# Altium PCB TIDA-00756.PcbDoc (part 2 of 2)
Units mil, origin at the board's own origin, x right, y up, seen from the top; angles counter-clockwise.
Board outline 4100 x 1700 mil, 4 copper layers (Top Layer, Signal Layer 1, Signal Layer 2, Bottom Layer), stack 43.668 mil thick; 130 components, 51 nets, 280 pads, 420 vias.
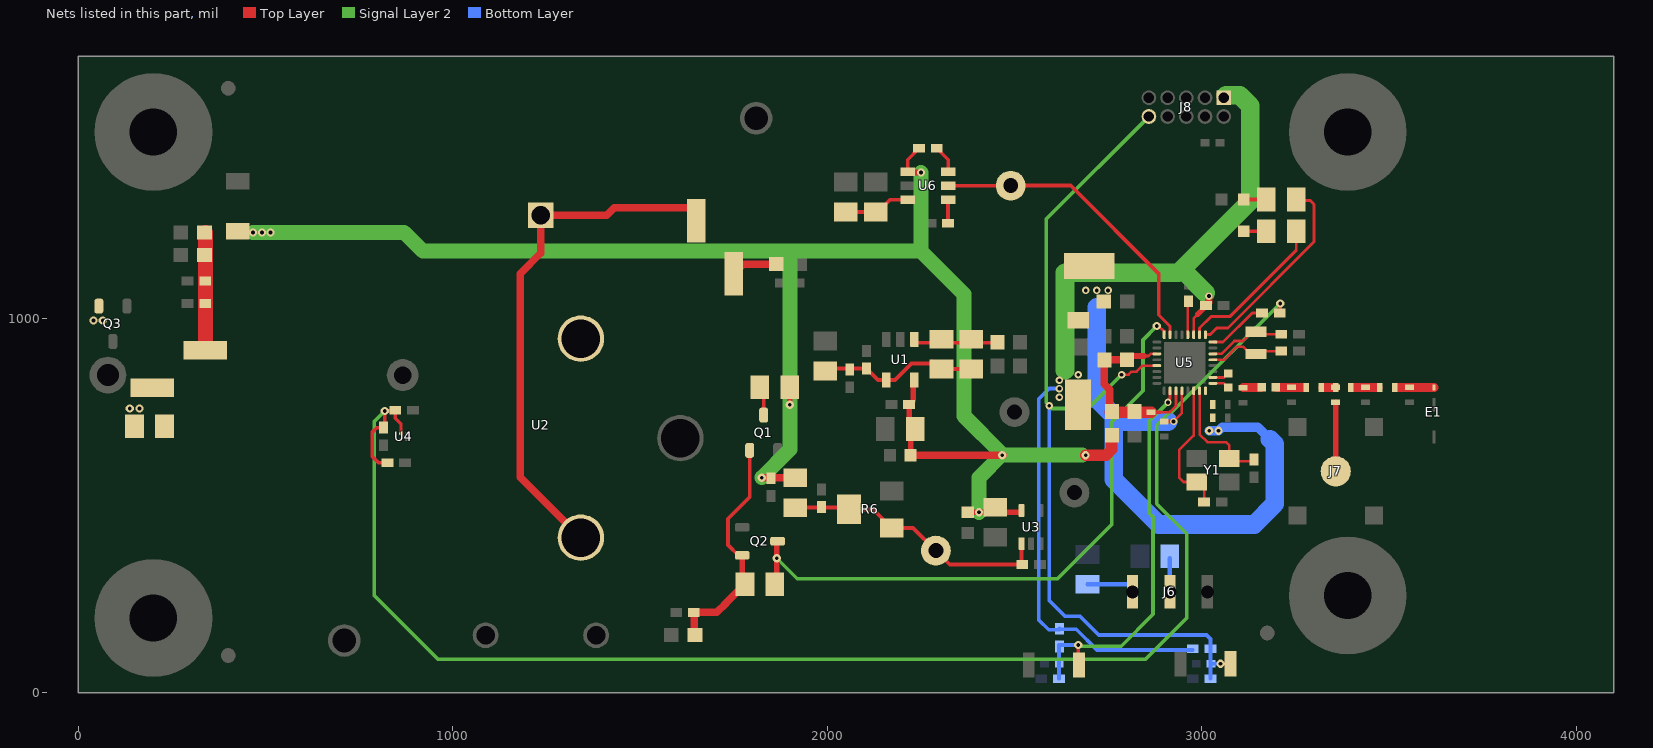
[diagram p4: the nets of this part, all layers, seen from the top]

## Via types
v1: diameter 26, hole 10, Top Layer to Bottom Layer, tented both sides, 253 vias
v2: diameter 20, hole 10, Top Layer to Bottom Layer, tented both sides, 105 vias
v3: diameter 22, hole 10, Top Layer to Bottom Layer, tented both sides, 57 vias
v4: diameter 19.68, hole 7.87, Top Layer to Bottom Layer, 5 vias

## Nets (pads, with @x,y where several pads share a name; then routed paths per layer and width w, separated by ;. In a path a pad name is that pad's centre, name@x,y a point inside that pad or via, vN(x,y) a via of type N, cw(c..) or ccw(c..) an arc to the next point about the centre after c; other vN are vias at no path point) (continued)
NetC6_1: C6.1 Q1.1 Q2.2 R3.2 R5.1 | length 633
  Top Layer w10: Q2.2@1772.76,367.6 1771.54,366.38 1763.62,366.38 1735,395 1735,465 1792.6,522.6 Q1.1@1792.6,647.76
  Top Layer w15: R5.1@1772.76,297.24 Q2.2@1772.76,367.6
  Top Layer w20: C6.1@1643.62,215 C6.1@1645,215 ; R3.2@1645,153.62 C6.1@1645,215 ; 1725,235 R5.1@1780,290 ; 1730,240 1705,215 C6.1@1645,215
NetC21_1: C21.1 R13.1 R14.1 | length 34
  Top Layer w24: C21.1@3324,816.3 R14.1@3358,816.3
NetC21_2: C21.2 C24.1 L2.2 | length 74.4
  Top Layer w24: L2.2@3199.65,816.3 C24.1@3240,816.3 C21.2@3274,816.3
NetC23_1: C23.1 L1.2 L2.1 U5.1 | length 90.3
  Top Layer w7: U5.1@3029.8,826.88 3059.12,826.88 L1.2@3069.7,816.3
  Top Layer w24: C23.1@3112,816.3 L2.1@3158,816.3
NetC25_2: C25.2 R14.2 R15.1 | length 68
  Top Layer w24: R14.2@3403,816.3 C25.2@3437,816.3 R15.1@3471,816.3
NetC26_2: C26.2 E1.1 R15.2 | length 99.3
  Top Layer w24: R15.2@3521,816.3 C26.2@3555,816.3 E1.1@3620.31,816.3
NetC27_1: C27.1 U5.12 | length 89.6
  Top Layer w7: U5.12@2962.87,956.8 C27.1@2962.87,1046.38
NetD1_1: D1.1 R22.2 | length 60.4
  Top Layer w10: D1.1@3112.09,1317.87 R22.2@3172.44,1317.87
NetD2_1: D2.1 R23.2 | length 60.4
  Top Layer w10: D2.1@3112.09,1232.87 R23.2@3172.44,1232.87
NetJ1_2: J1.2 R1.1 | length 124.2
  Top Layer w20: J1.2@1750,1119.13 1775.87,1145 R1.1@1863.5,1145
NetJ2_1: J2.1 R7.2
NetJ7_1: J7.1 R13.2 | length 184.7
  Top Layer w15: J7.1@3358,591.63 R13.2@3358,776.3
NetL1_1: L1.1 U5.2 | length 45.5
  Top Layer w7: U5.2@3029.8,842.63 3059.63,842.63 L1.1@3070.7,853.7
NetQ1_3: Q1.3 R2.2 | length 77.8
  Top Layer w10: Q1.3@1830,742.24 R2.2@1830,820
NetQ3_2: Q3.2 R7.1
  other v3: 137,760 163,760 40,995 65,995
NetR11_1: R11.1 U5.8 | length 163.8
  Top Layer w7.8: U5.8@3029.8,937.12 3057.12,937.12 3135,1015 R11.1@3161.38,1015
NetR16_1: R16.1 U6.6 | length 75.2
  Top Layer w10: R16.1@2292.56,1454.69 2323.07,1424.17 U6.6@2323.07,1392.09
NetR17_2: R17.2 R18.1 U6.3 | length 179.4
  Top Layer w10: R17.2@2048.94,1284.68 R18.1@2128.94,1284.69 2134.69,1284.69 2167.28,1317.28 U6.3@2214.8,1317.28
NetR19_2: R19.2 U6.4 | length 62.8
  Top Layer w10: R19.2@2322.56,1254.69 2322.56,1316.77 U6.4@2323.07,1317.28
NRESET: C36.2 J8.10 R21.1 S2.2 U5.21 U10.1 | length 2378.6
  Top Layer w7: v2(2786,850) 2805,850 2813,858 2826,858 2842.13,874.13 U5.21@2880.2,874.13
  Top Layer w10: v3(3050,78) S2.2@3076.93,78
  Signal Layer 2 w10: v2(2786,850) 2696,760 2600,760 v2(2593,767) 2585,775 2585,1265.75 J8.10@2858.94,1539.69
  Bottom Layer w10: v2(2593,767) 2593,247 2635,205 2675,205 2725,155 3013,155 3023.62,144.38 R21.1@3023.62,118 C36.2@3023.62,38 ; U10.1@3024.68,78 v3(3050,78)
RE: J5.1
RLED: R22.1 U5.9 | length 543.9
  Top Layer w7.8: U5.9@3010.12,956.8 3021.8,956.8 3040,975 3070,975 3300,1205 3300,1305 3290,1315 3260,1315 R22.1@3255,1310
SENSOR_TEST: Q2.3 R5.2 U5.16 | length 1707.8
  Top Layer w7.8: v3@2885,980 2899.88,965.12 U5.16@2899.88,956.8
  Top Layer w8: v3(2880,980) v3@2885,980
  Top Layer w10: Q2.3@1865,402.76 Q2.3@1867.24,405
  Top Layer w15: R5.2@1865,290 v3(1865,360) Q2.3@1865,402.76
  Signal Layer 2 w10: v3(1865,360) 1920,305 2615,305 2760,450 2760,724 2843,807 2843,943 v3(2880,980)
THRESH: C5.2 C8.1 R4.1 R6.1 R6.2 TP3.1 U3.1 | length 717
  Top Layer w10: R4.1@1920,495 R6.2@2050,495 ; R6.2@2057.91,490 2122.87,490 R6.1@2172.09,440.79 ; R6.1@2175,437.87 2175,440 2172.87,440 R6.1@2172.09,440.79 ; U3.1@2518.91,398.71 2518.91,344.97 C5.2@2520.88,343 ; C5.2@2520,342.12 C5.2@2520.88,343 ; R6.1@2172.09,440.79 2229.21,440.79 TP3.1@2290,380 2327,343 C5.2@2520.88,343
TIA_IN: C1.2 C3.1 CF1.2 RF1.1 RL1.2 U1.4 | length 456.5
  Top Layer w10: RL1.2@1995,873.62 2002.24,866.38 C3.1@2105,866.38 2135.67,835.71 2180.71,835.71 2225,880 2290,880 RF1.1@2300,870 ; RF1.1@2280,885 2300,865 RF1.1@2305,865 CF1.2@2385,865
TIA_OUT: CF1.1 RF1.2 RO1.1 U1.1 | length 205.6
  Top Layer w10: U1.1@2235,935 RO1.1@2436.61,935 ; RO1.1@2452.2,939.29 RO1.1@2455,936.5
UART_RX: J6.1 R10.1 | length 150
  Bottom Layer w12: R10.1@2695,290 2815,290 J6.1@2815,260
UART_TX: J6.2 R12.1 | length 100
  Bottom Layer w12: J6.2@2915,260 R12.1@2915,360
USR_BTN: C35.2 R20.1 S1.2 U5.26 U9.1 | length 1052.6
  Top Layer w7.8: v2@2906,776 2915.63,785.63 U5.26@2915.63,807.2
  Top Layer w10: S1.2@2670,75 v3@2670,129.93
  Signal Layer 2 w10: v3@2675,125 2785,125 2870,210 2870,470 2860,480 2860,726 v2(2910,776)
  Bottom Layer w10: C35.2@2618.62,38 2618.62,128 v3(2670,128)
V_BATT: C7.1 C9.2 C10.2 C11.1 C12.2 C13.2 C14.1 C15.1 C16.1 C17.1 C18.1 J2.2 L3.1 R2.1 R4.2 R16.2 U1.5 U3.5 U6.1 | length 4929.7
  Top Layer w10: U6.1@2214.8,1392.09 2214.8,1424.17 R16.2@2245.31,1454.69 ; U3.5@2514.18,482.56 U3.5@2518.91,487.29
  Top Layer w15: v3(1900,770) R2.1@1900,816.12 ; U6.1@2216.89,1390 v3(2250,1390) ; C9.2@2222.56,635 2222.56,692.56 C10.2@2235,705 2218.62,721.38 C11.1@2218.62,770 2230,781.38 U1.5@2230,826.3 ; C12.2@2385,482.56 v3(2405,482.56) U3.5@2514.18,482.56
  Top Layer w20: v3(1825,575) R4.2@1905,575 ; C9.2@2222.56,635 v3(2467.56,635) v3@2470,635
  Top Layer w30: v3(2690,635) 2745,635 2760,650 L3.1@2760,688.5
  Top Layer w40: J2.2@339,928 C15.1@339,1230
  Signal Layer 2 w40: v3(466,1230) 870,1230 920,1180 2250,1180 v3(2250,1390) ; v3(1825,575) 1900,650 1900,1180 ; 2245,1185 2365,1065 2365,740 2467.5,637.5 2405,575 v3(2405,482.56) ; v3@2465,635 v3@2681,635
  other v3: 490,1230 513,1230
VCC_I2C: C19.1 R8.2 R9.2 R11.2 U4.A1 | length 4114.6
  Top Layer w8: U4.A1@860.83,694 860.83,719.17
  Top Layer w10: R9.2@815,708.62 818,711.62 v3(818,753) 837,753 C19.1@839,755 ; R9.2@818.7,708.54 796.54,708.54 785,697 785,631 801.08,614.92 R8.2@825.08,614.92 ; C19.1@846.38,755 846.38,733.62 860.83,719.17 ; R11.2@3208.62,1015 3210,1016.38 v3(3210,1040)
  Signal Layer 2 w10: v3(818,753) 790,725 790,260 960,90 2850,90 2960,200 2960,425 2880,505 2880,715 2916,751 2921,751 v3(3210,1040)
VDDR: C37.2 C38.1 C39.1 C40.1 L4.2 TP8.1 U5.28 U5.32 | length 1585.3
  Top Layer w7: v2(2925,725) 2947.13,747.13 U5.28@2947.13,807.2
  Top Layer w12: C40.1@2900,725 v2(2925,725)
  Bottom Layer w25: v3(3020,700) v3(3045,700) 3055,710 3150,710 3182.5,677.5
  Bottom Layer w50: 2720,1030 2720,785 2765,740 2765,570 2885,450 3140,450 3195,505 3195,665 3182.5,677.5 ; 2780,725 2910,725
  other v2: 2690,1075 2720,1075 2750,1075
VDDS: C30.1 C31.1 C32.1 C33.2 C34.2 J8.1 L3.2 R20.2 R21.2 TP7.1 U5.11 U5.19 U5.27 | length 2967.2
  Top Layer w7: 2846,900 2858,900 2863.62,905.62 U5.19@2880.2,905.62 ; 2890,750 2915,750 2931.38,766.38 U5.27@2931.38,807.2 ; U5.11@2978.62,956.8 2978.62,1000.6 2989.93,1011.9
  Top Layer w10: C31.1@2865,750 2890,750
  Top Layer w15: C33.2@2809.5,900 2846,900 ; 2989.93,1011.9 C32.1@3019.38,1041.98
  Top Layer w20: L3.2@2755,750 2755,810 2740,825 C34.2@2740,889.5 C33.2@2800,889.5 ; C32.1@3019.38,1041.98 v2(3019.38,1060)
  Top Layer w30: L3.2@2755,750 C31.1@2865,750
  Signal Layer 2 w50: 2635,862 2635,1122 2938,1122 ; 3011,1068 2947.5,1131.5 3130,1314 3130,1568 3102,1596 J8.1@3065,1596
  Bottom Layer w10: R20.2@2620,168.62 2591.38,168.62 2565,195 2565,785 2593,813 v2(2620,813) ; R20.2@2620,170 2665,170 2720,115 R21.2@2976.38,115 ; R20.2@2620,171.62 R20.2@2620,173
  other v2: 2620,790 2620,835 2670,850
WAKE_INT: TP6.1 U5.15 U6.5 | length 837.2
  Top Layer w7.8: 2885,1010 2915.63,979.37 U5.15@2915.63,956.8
  Top Layer w10: U6.5@2323.07,1354.69 TP6.1@2490,1354.69 ; TP6.1@2490,1350 2495,1355 2650,1355 2885,1120 2885,1010
WE: J1.1 J3.1 U2.1 | length 1369.4
  Top Layer w20: J3.1@1341.93,414.68 1180,576.61 1180,1120 1235,1175 U2.1@1235,1276.02 1411.02,1276.02 1430.87,1295.87 J1.1@1645,1295.87
X24M_N: C22.2 U5.30 Y1.3 | length 333.5
  Top Layer w7: U5.30@2978.62,807.2 2978.62,687.62 2940,649 2940,575 2951.5,563.5 Y1.3@2986.69,563.5 ; C22.2@3006.38,510 Y1.3@3006.38,543.82
X24M_P: C20.2 U5.31 Y1.1 | length 296.5
  Top Layer w7: U5.31@2994.37,807.2 2994.37,690.63 3015,670 3065,670 3073.31,661.69 Y1.1@3073.31,626.5 ; Y1.1@3081.18,618.62 C20.2@3135,618.62
X32K_Q1: C29.1 U5.5 Y2.1 | length 181.8
  Top Layer w7: U5.5@3029.8,889.87 3059.5,889.87 3094.62,925 3109.62,925 ; 3110,925 Y2.1@3129.53,905.47 ; Y2.1@3152.53,913 C29.1@3212.38,913
X32K_Q2: C28.1 U5.6 Y2.2 | length 189.6
  Top Layer w7: U5.6@3029.8,905.62 3052.97,905.62 3087.35,940 3109.62,940 ; 3110,940 Y2.2@3134.53,964.53 ; Y2.2@3151.53,958 C28.1@3212.38,958
YLED: R23.1 U5.10 | length 412.3
  Top Layer w7.8: U5.10@2994.37,956.8 2994.37,974.37 3025,1005 3075,1005 3252.44,1182.44 R23.1@3252.44,1232.87
pads on no net: FID1.1 FID2.1 FID3.1 FID4.1 FID5.1 FID6.1 J8.6 J8.7 J8.8 SH-J1.0 SH-J2.0 U5.4

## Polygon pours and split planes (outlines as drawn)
GND on Signal Layer 1 "Top Layer-No Net" (solid, remove dead copper, pour order 10): 25,1675 3600,1675 3600,25 25,25
GND on Signal Layer 1 "Top Layer-No Net" (solid, remove dead copper, shelved, pour order 2): 25,1675 3600,1675 3600,25 25,25
GND on Top Layer "Top Layer-No Net" (solid, remove dead copper, pour order 4): 25,1675 3600,1675 3600,25 25,25
GND on Signal Layer 2 "Top Layer-No Net" (solid, remove dead copper, pour order 8): 25,1675 3600,1675 3600,25 25,25
GND on Bottom Layer "Top Layer-No Net" (solid, remove dead copper, pour order 6): 25,1675 3600,1675 3600,25 25,25

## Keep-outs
Keep-Out Layer:
  lines w10: -5,0 ccw(c0,0) 0,-5 ; -5,0 ccw(c0,0) 0,-5 ; -5,0 -5,1700 ; -5,1700 cw(c0,1700) 0,1705 ; -5,1700 cw(c0,1700) 0,1705 ; 0,-5 4100,-5 ; 0,1705 4100,1705 ; 4100,-5 ccw(c4100,0) 4105,0 ; 4100,-5 ccw(c4100,0) 4105,0 ; 4100,1705 cw(c4100,1700) 4105,1700 ; 4100,1705 cw(c4100,1700) 4105,1700 ; 4105,0 4105,1700
  text ".Layer_Name" at 577,-858.49 h60

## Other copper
Top Layer:
  rectangle net UART_RX: 2790,225 2840,315
  rectangle net UART_TX: 2890,225 2940,315
  rectangle net NetBT1_1: 51.18,850 105,960
  rectangle net V_BATT: 315,1210 525,1250
  rectangle net NetJ2_1: 205,719 255,839
  rectangle net NetQ3_2: 25,980 80,1055
  rectangle net NetQ3_2: 125,680 175,771
  region net GND: 2718,933 2718,993 2735,1010 2765,1010 2780,1025 2780,1065 2825,1065 2845,1045 2845,986 2892,939 2899,939 2902,936 2902,926 2895,933
  region net GND: 3604.49,840.48 3604.49,1414.71 3554.92,1414.71 3554.92,879.71 3099.92,879.71 3099.92,840.48
  region net GND: 3604.49,79.71 3554.92,79.71 3554.92,789.71 3604.49,789.71
  region net GND: 3619.92,663.78 3600.86,663.78 3594.92,669.71 3594.92,694.71 3602.35,702.15 3619.92,702.15
  region net GND: 3619.92,750.39 3599.24,750.39 3594.92,754.71 3594.92,779.71 3603.97,788.76 3619.92,788.76
  pour cut-out: 2865,785 2600,785 2515,785 2375,785 2375,895 2625,895 2865,895
  pour cut-out: 2630,930 2895,930 2895,1040 2840,1095 2630,1095
  region net VDDR: 3006.2,819 3006.2,699 3015.2,690 3050.2,690 3055.2,695 3055.2,705 3040.2,720 3040.2,791 3012.2,819
  region net VDDS: 2705,705 2710,710 2725,725 2835,725 2850,740 2850,760 2835,775 2705,775 2705,850 2695,860 2630,860 2610,840 2610,780 2635,755 2635,705
  region net VDDR: 2760,1025 2760,1080 2760,1170 2640,1170 2640,1040 2640,970 2700,970 2700,1005 2720,1025
  region net NetC23_1: 3114,804.3 3059,804.3 3059,828.3 3114,828.3
  pour cut-out: 3604.57,790 3382,790 3382,632 3380,630 3340,630 3334,636 3334,790 3056,790 3048,798 3048,823 3065.77,840.77 3604.57,840.77
  pour cut-out: 3605,60 4093.19,60 4093.19,1437.95 3605,1437.95
  region net GND: 3035,495 3035,590 3150,590 3150,515 3130,495
  pour cut-out: 2955,820 2955,720 2925,690 2925,545 2975,495 3130,495 3150,515 3150,650 3125,675 3016,675 2999,692 2999,820 3009,820 3009,696 3020,685 3130,685 3160,655 3160,510 3135,485 2970,485 2915,540 2915,695 2945,725 2945,829 3009,829 3009,820
  pour cut-out: 3190,430 3520,430 3520,755 3190,755
  text ".Layer_Name" at 577,-858.49 h60
Signal Layer 1:
  rectangle net UART_TX: 2890,225 2940,315
  rectangle net UART_RX: 2790,225 2840,315
  region net GND: 3130,495 2975,495 2925,545 2925,690 2955,720 2955,820 2999,820 2999,692 3016,675 3125,675 3150,650 3150,515
  pour cut-out: 2955,820 2955,720 2925,690 2925,545 2975,495 3130,495 3150,515 3150,650 3125,675 3016,675 2999,692 2999,820 3009,820 3009,696 3020,685 3130,685 3160,655 3160,510 3135,485 2970,485 2915,540 2915,695 2945,725 2945,829 3009,829 3009,820
  pour cut-out: 3604.57,60 4092.76,60 4092.76,1437.95 3604.57,1437.95
  text ".Layer_Name" at 577,-858.49 h60
Signal Layer 2:
  rectangle net UART_TX: 2890,225 2940,315
  rectangle net UART_RX: 2790,225 2840,315
  rectangle net VDDS: 2610,780 2680,885
  region net NetQ3_2: 25,990 85,930 110,930 150,890 150,810 120,780 120,745 205,745 205,920 110,1015 25,1015
  pour cut-out: 2955,820 2955,720 2925,690 2925,545 2975,495 3130,495 3150,515 3150,650 3125,675 3016,675 2999,692 2999,820 3009,820 3009,696 3020,685 3130,685 3160,655 3160,510 3135,485 2970,485 2915,540 2915,695 2945,725 2945,829 3009,829 3009,820
  text ".Layer_Name" at 577,-858.49 h60
Bottom Layer:
  rectangle net UART_RX: 2790,225 2840,315
  rectangle net UART_TX: 2890,225 2940,315
  region net VDDR: 2700,1015 2680,1035 2680,1085 2760,1085 2760,1035 2740,1015
  pour cut-out: 2955,820 2955,720 2925,690 2925,545 2975,495 3130,495 3150,515 3150,650 3125,675 3016,675 2999,692 2999,820 3009,820 3009,696 3020,685 3130,685 3160,655 3160,510 3135,485 2970,485 2915,540 2915,695 2945,725 2945,829 3009,829 3009,820
  text ".Layer_Name" at 577,-858.49 h60

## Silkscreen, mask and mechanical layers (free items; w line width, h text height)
Top Overlay:
  circle w10: c1339.96,684.37 r401.57
  region: 1465,1433 1165,1433 1165,1333 1465,1333
  text "'.PRJ_Number'.PCB_Rev-" at 630,1348.77 h108.27
  text "RE" at 1305,800 h60
  text "CE" at 1570,785 h60
  text "WE" at 1375,505 h60
  text "RX" at 2780,330 h60
  text "TX" at 2880,330 h60
  text "GND" at 2970,330 h60
  text "RESET" at 2736,55 h60
  text "USER" at 2359,54 h60
  text ".Layer_Name" at 577,-858.49 h60
Bottom Overlay:
  text ".Layer_Name" at 577,-858.49 h60
Top Paste:
  text ".Layer_Name" at 577,-858.49 h60
Bottom Paste:
  text ".Layer_Name" at 577,-858.49 h60
Top Solder:
  text ".Layer_Name" at 577,-858.49 h60
  text ".Layer_Name" at 577,-858.49 h60
Bottom Solder:
  text ".Layer_Name" at 577,-858.49 h60
Drill Guide:
  text ".Layer_Name" at 577,-858.49 h60
M1 Board Outline:
  the board outline again, w10
  text ".Layer_Name" at 577,-858.49 h60
M2 Board Dimensions:
  rectangle: 0,-275 125,-150
  rectangle: 125,-400 500,-275
  lines w7: 0,-275 1000,-275 ; 125,-400 125,-150 ; 250,-400 250,-150 ; 500,-400 500,-150 ; 750,-400 750,-150 ; 0,-400 1000,-400 1000,-150 0,-150 0,-400
  text ".Layer_Name" at 577,-858.49 h60
M3 3D STEP Top:
  text ".Layer_Name" at 577,-858.49 h60
M4 3D STEP Bottom:
  text ".Layer_Name" at 577,-858.49 h60
M5 Assembly Top:
  lines w10: -292,-930.17 6308,-930.17 ; -292,-726.83 6310,-726.83 ; -292,-523.5 -292,-1133.5 3713,-1133.5 6310,-1133.5 6310,-523.5 -291.5,-523.5 -291.5,-1133.5 1284,-1133.5 ; 2173,-1133.5 2173,-523.5 ; 3440,-726.83 3440,-523.5 ; 4280,-726.83 4280,-523.5 ; 4902,-1140 4902,-937.17
  text "COMPONENTS MARKED 'DNP' SHOULD NOT BE POPULATED." at 1153.5,-318.5 h60
  text "ASSEMBLY VARIANT:" at 1153,-434 h60
  text ".VariantName" at 2189,-434 h60
  text "PCB VIEWED FROM TOP SIDE" at -228.5,-655.67 h60
  text "BOARD #:" at 2248,-655.67 h60
  text ".PRJ_Number" at 2793.5,-655.67 h60
  text "REV:" at 3638,-655.67 h60
  text ".PCB_Rev" at 3929.5,-655.67 h60
  text "SVN REV:" at 4476,-655.67 h60
  text ".VersionControl_RevNumber" at 4982,-655.67 h60
  text "TID #:" at 2248,-859 h60
  text ".TID" at 2793.5,-859 h60
  text "PLOT NAME =" at -228.5,-1064.34 h60
  text ".plot_File_Name" at 577,-1064.34 h60
  text "GENERATED    :" at 2250,-1064.34 h60
  text ".Print_Date" at 3119.5,-1064.34 h60
  text ".Print_Time" at 3848.5,-1064.34 h60
  text "TEXAS INSTRUMENTS" at 5113,-1064.34 h60
M6 Assembly Bottom:
  lines w10: -292.5,-727.33 6309.5,-727.33 ; -290.5,-930.67 6309.5,-930.67 ; 1115.5,-1140.5 1115.5,-937.67 ; 1737.5,-727.33 1737.5,-524 ; 2577.5,-727.33 2577.5,-524 ; 3844.5,-1134 3844.5,-524 ; 4733.5,-1134 6309,-1134 6309,-524 -292.5,-524 -292.5,-1134 2304.5,-1134 6309.5,-1134 6309.5,-524
  text "COMPONENTS MARKED 'DNP' SHOULD NOT BE POPULATED." at 6102,-318 h60
  text ".VariantName" at 5058,-434 h60
  text "ASSEMBLY VARIANT:" at 6097,-434 h60
  text ".VersionControl_RevNumber" at 1035.5,-656.17 h60
  text "SVN REV:" at 1541.5,-656.17 h60
  text ".PCB_Rev" at 2088,-656.17 h60
  text "REV:" at 2379.5,-656.17 h60
  text ".PRJ_Number" at 3224,-656.17 h60
  text "BOARD #:" at 3769.5,-656.17 h60
  text "PCB VIEWED FROM BOTTOM SIDE" at 6246,-656.17 h60
  text ".TID" at 3224,-859.5 h60
  text "TID #:" at 3769.5,-859.5 h60
  text "TEXAS INSTRUMENTS" at 904.5,-1064.84 h60
  text ".Print_Time" at 2169,-1064.84 h60
  text ".Print_Date" at 2898,-1064.84 h60
  text "GENERATED    :" at 3767.5,-1064.84 h60
  text ".plot_File_Name" at 5440.5,-1064.84 h60
  text "PLOT NAME =" at 6246,-1064.84 h60
M9 Title Sheet:
  drawing of 57 lines, arcs and shapes, not listed
  text "1" at 739.84,8036.5 h70
  text "2" at 3235.5,8036.5 h70
  text "3" at 5724.84,8036.5 h70
  text "4" at 8231.51,8036.5 h70
  text "5" at 10730.5,8036.5 h70
  text "6" at 13235.5,8036.5 h70
  text "A" at -416.5,6893.5 h70
  text "A" at 14383.5,6893.5 h70
  text "B" at -416.5,4513.5 h70
  text "B" at 14383.5,4513.5 h70
  text "C" at -416.5,2138.5 h70
  text "C" at 14383.5,2138.5 h70
  text "PROJECT TITLE:" at 11343.5,277.5 h45
  text ".PRJ_Title" at 11393.5,144.17 h70
  text "DESIGNED FOR:" at 11343.5,-23.5 h45
  text ".PRJ_Customer" at 11393.5,-163.5 h70
  text "D" at -416.5,-231.5 h70
  text "D" at 14383.5,-231.5 h70
  text "FILE NAME:" at 11343.5,-323.5 h45
  text ".PCB_File_Name_No_Path" at 11393.5,-443.5 h70
  text "Texas Instruments (TI) and/or its licensors do not warrant the accuracy or completeness of this specification" at 6374,-605.34 h45
  text "ENGINEER:" at 11343.5,-613.5 h45
  text "LAYOUT BY:" at 12848.5,-613.5 h45
  text "or any information contained therein. TI and/or its licensors do not warrant that this design will meet" at 6329.01,-718 h45
  text ".PRJ_Engineer" at 11393.5,-768.49 h70
  text ".PCB_Layout" at 12899,-768.49 h70
  text "the specifications, will be suitable for your application or fit for any particular purpose, or will operate in" at 6329.01,-830.67 h45
  text ".Layer_Name" at 577,-858.49 h60
  text "ALTIUM DESIGNER VERSION:" at 12848.5,-923.5 h45
  text "an implementation. TI and/or its licensors do not warrant that the design is production worthy. You should" at 6329.01,-943.33 h45
  text "completely validate and test your design implementation to confirm the system functionality for your application." at 6374,-1056 h45
  text ".print_Scale" at 11393.5,-1056.83 h70
  text ".Application_BuildNumber" at 12899,-1056.83 h70
  text "1" at 739.84,-1263.5 h70
  text "2" at 3235.5,-1263.5 h70
  text "3" at 5724.84,-1263.5 h70
  text "4" at 8231.51,-1263.5 h70
  text "5" at 10730.5,-1263.5 h70
  text "6" at 13235.5,-1263.5 h70
M10 Fab Notes:
  drawing of 174 lines, arcs and shapes, not listed
  text "DESIGN INFORMATION" at 12378.02,6201 h60
  text "Impedance Control:" at 6927,6195 h200
  text "MIN. TRACK WIDTH:" at 11733.46,6021 h60
  text "6" at 12829.7,6021 h60
  text "MIL" at 12984.46,6021 h60
  text "- Top layer contains 50 ohm impedance (+/- 10%) single ended using 24 mil lines (from E1 to U5)" at 6927,5955 h100
  text "MIN. CLEARANCE:" at 11733.46,5889 h60
  text "6" at 12769.7,5889 h60
  text "MIL" at 12984.46,5889 h60
  text "MIN. VIA PAD SIZE:" at 11733.46,5757 h60
  text "20" at 12799.71,5757 h60
  text "MIL" at 12984.46,5757 h60
  text "0.05mm (2MIL)" at 12428.46,5615.29 h60
  text "MINIMUM ANNULAR RING" at 11404.23,5611 h60
  text "EXTERNAL" at 13136.46,5611 h60
  text "PER" at 11604.23,5493 h60
  text "IPC-D-275 CLASS 2 LEVEL C" at 11824.23,5493 h60
  text "MIL, HOLES" at 13312.46,5380.71 h60
  text "+/-" at 12920,5380 h60
  text "+/-" at 13774,5380 h60
  text "REGISTRATION TOLERANCES:" at 11404.23,5375 h60
  text "METAL" at 12604,5375 h60
  text "5" at 13180.2,5375 h60
  text "3" at 14013.2,5375 h60
  text "MIL" at 14129.46,5375 h60
  text "+/-" at 13774,5262 h60
  text "HOLE SIZE TOLERANCE (UNLESS OTHERWISE SPECIFIED):" at 11404.23,5257 h60
  text "3" at 14013.2,5257 h60
  text "MIL" at 14129.46,5257 h60
  text "MATERIAL:" at 11329.46,5047.54 h60
  text "FR-4 High Tg" at 12315.9,4907.21 h60
  text "FR-408" at 11750.46,4898.64 h60
  text "OTHER" at 13238.46,4898.64 h60
  text "X" at 12161,4895 h60
  text "62 MIL (1.6mm) +/-10%" at 12070.56,4735.92 h60
  text "44 MIL +/-10%" at 13630,4735 h60
  text "THICKNESS:" at 11404.23,4731.64 h60
  text "OTHER" at 13355.46,4731.64 h60
  text "X" at 13225,4725 h60
  text "TOLERANCE:" at 11404.23,4573.64 h60
  text "X" at 12243.53,4573.64 h60
  text "ANSI IPC-6012 TYPE 3 CLASS 2" at 12430.48,4573.64 h60
  text "OTHER +/-" at 12430.46,4417.64 h60
  text "BOW & TWIST:" at 11404.23,4260.64 h60
  text "X" at 12243.53,4260.64 h60
  text "ANSI IPC-6012 TYPE 3 CLASS 2" at 12430.48,4260.64 h60
  text "OTHER +/-" at 12430.46,4102.13 h60
  text "DRILLING:" at 11329.46,3963.64 h60
  text "REFERENCE:" at 11404.23,3846.64 h60
  text "X" at 12052.46,3846.64 h60
  text "AS SHOWN" at 12239.46,3846.64 h60
  text "X" at 12953.46,3846.64 h60
  text "NC_DRILL FILES" at 13090.46,3846.64 h60
  text "PTH COPPER THICKNESS:" at 11404.23,3688.64 h60
  text "X" at 12534.46,3688.64 h60
  text "20-30 um" at 12671.46,3688.64 h60
  text "OTHER" at 13388.46,3688.64 h60
  text "BOARD FINISH:" at 11329.46,3529.64 h60
  text "SILKSCREEN:" at 11484.68,3411.64 h60
  text "X" at 12433.46,3411.64 h60
  text "TOP" at 12559.46,3411.64 h60
  text "X" at 12943.46,3411.64 h60
  text "BOTTOM" at 13070.46,3411.64 h60
  text "SILKSCREEN COLOR:" at 11484.68,3244.64 h60
  text "X" at 12432.42,3244.64 h60
  text "WHITE" at 12559.46,3244.64 h60
  text "OTHER" at 13070.46,3244.64 h60
  text "X" at 12563.42,3085.44 h60
  text "GREEN" at 12690.46,3085.44 h60
  text "OTHER" at 13308.46,3085.44 h60
  text "SOLDER RESIST COLOR:" at 11484.68,3074.64 h60
  text "X" at 12563.42,2915.44 h60
  text "MATTE" at 12690.46,2915.44 h60
  text "SEMI-GLOSS" at 13308,2914.8 h60
  text "IMMERSION GOLD (ENIG)" at 12390.46,2726.92 h60
  text "ENEPIG" at 13728,2723.64 h60
  text "SURFACE FINISH:" at 11329.46,2722.64 h60
  text "X" at 12203.51,2722.64 h60
  text "IMM. TIN/SILVER OR EQUIV" at 11659,2565.64 h60
  text "OTHER" at 13090.46,2565.64 h60
  text "ARRAY/PANEL:" at 11329.46,2386.64 h60
  text "CUT AND TRIM PER M1 BOARD OUTLINE" at 12390.46,2382.35 h60
  text "N.C. ROUTE" at 12390.46,2230.64 h60
  text "X" at 13069.46,2230.64 h60
  text "V. SCORE" at 13256.46,2230.64 h60
  text "CERTIFICATION:" at 11329.46,2093.64 h60
  text "MATERIALS AND WORKMANSHIP FOR ALL PCBS" at 12054.46,2093.64 h60
  text "TO MEET OR EXCEED THE REQUIREMENTS OF:" at 12054.46,1995.64 h60
  text "X" at 11680.96,1859.13 h60
  text "ANSI IPC-A-600F CLASS ->" at 11819.96,1859.13 h60
  text "X" at 13459.02,1859.13 h60
  text "2" at 13577.96,1859.14 h60
  text "1" at 13262.96,1857.64 h60
  text "3" at 13931.96,1857.64 h60
  text "X" at 12495.02,1699.64 h60
  text "RoHS" at 12631.96,1699.64 h60
  text "OTHER" at 13276.36,1699.64 h60
  text "PER ORDER" at 13673.42,1699.64 h60
  text "ALL BOARDS MUST MEET OR EXCEED UL94-V0 REQUIREMENTS." at 11357,1534 h60
  text "PCB MUST BEAR THE UL94V-0 UL REGISTERED MATERIAL ID NUMBER" at 11357,1414 h60
  text "ADDITIONAL REQUIREMENTS:" at 11329.46,1240.64 h60
  text "MICROSECTION:" at 11404.23,1125.64 h60
  text "YES" at 12309.96,1125.64 h60
  text "REQUIRED" at 13171.46,969.49 h60
  text "BARE BOARD ELEC. TEST:" at 11404.23,966.64 h60
  text "NONE" at 12709.96,966.64 h60
  text "X" at 13044.46,966.64 h60
  text "PER ORDER" at 13763.46,966.64 h60
  text ".Layer_Name" at 577,-858.49 h60
M11 Gerber Information:
  lines w10: -292,-930.17 6308,-930.17 ; -292,-726.83 6310,-726.83 ; -292,-523.5 -292,-1133.5 3713,-1133.5 6310,-1133.5 6310,-523.5 -291.5,-523.5 -291.5,-1133.5 1284,-1133.5 ; 2173,-1133.5 2173,-523.5 ; 3440,-726.83 3440,-523.5 ; 4280,-726.83 4280,-523.5 ; 4902,-1140 4902,-937.17
  text "ALL ARTWORK VIEWED FROM TOP SIDE" at -228.5,-655.67 h60
  text "BOARD #:" at 2248,-655.67 h60
  text ".PRJ_Number" at 2793.5,-655.67 h60
  text "REV:" at 3638,-655.67 h60
  text ".PCB_Rev" at 3929.5,-655.67 h60
  text "SVN REV:" at 4476,-655.67 h60
  text ".VersionControl_RevNumber" at 4982,-655.67 h60
  text "LAYER NAME =" at -228.5,-858.49 h60
  text "TID #:" at 2248,-859 h60
  text ".TID" at 2793.5,-859 h60
  text "PLOT NAME =" at -228.5,-1064.34 h60
  text ".plot_File_Name" at 577,-1064.34 h60
  text "GENERATED    :" at 2250,-1064.34 h60
  text ".Print_Date" at 3119.5,-1064.34 h60
  text ".Print_Time" at 3848.5,-1064.34 h60
  text "TEXAS INSTRUMENTS" at 5113,-1064.34 h60
M12 Stackup:
  drawing of 295 lines, arcs and shapes, not listed
  text "Layer" at 9727.5,7787.5 h60
  text "Name" at 10137.41,7787.5 h60
  text "Material" at 11077.15,7787.5 h60
  text "Thickness" at 11936.92,7787.5 h60
  text "Constant" at 12586.76,7787.5 h60
  text "Board Layer Stack" at 13156.62,7787.5 h60
  text "1" at 9727.5,7667.5 h60
  text "Top Overlay" at 10137.41,7667.5 h60
  text "2" at 9727.5,7547.5 h60
  text "Top Solder" at 10137.41,7547.5 h60
  text "Solder Resist" at 11077.15,7547.5 h60
  text "0.40mil" at 11936.92,7547.5 h60
  text "3.5" at 12586.76,7547.5 h60
  text "3" at 9727.5,7427.5 h60
  text "Top Layer" at 10137.41,7427.5 h60
  text "Copper" at 11077.15,7427.5 h60
  text "1.42mil" at 11936.92,7427.5 h60
  text "4" at 9727.5,7307.5 h60
  text "Dielectric1" at 10137.41,7307.5 h60
  text "370HR" at 11077.15,7307.5 h60
  text "14.00mil" at 11936.92,7307.5 h60
  text "4.2" at 12586.76,7307.5 h60
  text "5" at 9727.5,7187.5 h60
  text "Signal Layer 1" at 10137.41,7187.5 h60
  text "Copper" at 11077.15,7187.5 h60
  text "1.42mil" at 11936.92,7187.5 h60
  text "6" at 9727.5,7067.5 h60
  text "Dielectric 2" at 10137.41,7067.5 h60
  text "370HR" at 11077.15,7067.5 h60
  text "10.00mil" at 11936.92,7067.5 h60
  text "4.2" at 12586.76,7067.5 h60
  text "7" at 9727.5,6947.5 h60
  text "Signal Layer 2" at 10137.41,6947.5 h60
  text "Copper" at 11077.15,6947.5 h60
  text "1.42mil" at 11936.92,6947.5 h60
  text "8" at 9727.5,6827.5 h60
  text "Dielectric 3" at 10137.41,6827.5 h60
  text "370HR" at 11077.15,6827.5 h60
  text "14.00mil" at 11936.92,6827.5 h60
  text "4.2" at 12586.76,6827.5 h60
  text "9" at 9727.5,6707.5 h60
  text "Bottom Layer" at 10137.41,6707.5 h60
  text "Copper" at 11077.15,6707.5 h60
  text "1.42mil" at 11936.92,6707.5 h60
  text "10" at 9727.5,6587.5 h60
  text "Bottom Solder" at 10137.41,6587.5 h60
  text "Solder Resist" at 11077.15,6587.5 h60
  text "0.40mil" at 11936.92,6587.5 h60
  text "3.5" at 12586.76,6587.5 h60
  text "11" at 9727.5,6467.5 h60
  text "Bottom Overlay" at 10137.41,6467.5 h60
  text ".Layer_Name" at 577,-858.49 h60
M13 Component Bodies Top:
  text ".Layer_Name" at 577,-858.49 h60
M14 Component Bodies Bottom:
  text ".Layer_Name" at 577,-858.49 h60
M15 Courtyards Top:
  text ".Layer_Name" at 577,-858.49 h60
M16 Courtyards Bottom:
  text ".Layer_Name" at 577,-858.49 h60
Drill Drawing:
  circle w10: c5348.65,2509.7 r13.23
  circle w10: c5348.65,2509.7 r22.05
  circle w10: c5348.65,2311.28 r22.05
  lines w10: 5326.6,2399.46 5337.63,2399.46 5348.65,2388.44 5359.68,2399.46 5370.7,2399.46 5359.68,2410.49 5370.7,2421.51 5359.68,2421.51 5348.65,2432.53 5337.63,2421.51 5326.6,2421.51 5337.63,2410.49 5326.6,2399.46 ; 5326.6,2586.86 5348.65,2597.89 5370.7,2586.86 5359.68,2608.91 5370.7,2630.96 5348.65,2619.93 5326.6,2630.96 5337.63,2608.91 5326.6,2586.86 ; 5326.6,2686.07 5326.6,2697.1 5337.63,2708.12 5326.6,2719.14 5326.6,2730.17 5337.63,2730.17 5348.65,2719.14 5359.68,2730.17 5370.7,2730.17 5370.7,2719.14 5359.68,2708.12 5370.7,2697.1 5370.7,2686.07 5359.68,2686.07 5348.65,2697.1 5337.63,2686.07 5326.6,2686.07 ; 5326.6,2796.31 5337.63,2796.31 5337.63,2785.29 5359.68,2785.29 5359.68,2796.31 5370.7,2796.31 5370.7,2818.36 5359.68,2818.36 5359.68,2829.38 5337.63,2829.38 5337.63,2818.36 5326.6,2818.36 5326.6,2796.31 ; 5326.6,2884.5 5370.7,2884.5 5370.7,2928.59 5326.6,2928.59 5326.6,2884.5 ; 5326.6,3027.8 5370.7,3027.8 5348.65,2983.71 5326.6,3027.8 ; 5326.6,3127.01 5370.7,3127.01 5348.65,3082.92 5326.6,3127.01 ; 5326.6,3182.13 5370.7,3182.13 5370.7,3226.22 5326.6,3226.22 5326.6,3182.13 ; 5326.6,3303.39 5348.65,3281.34 5370.7,3303.39 5348.65,3325.43 5326.6,3303.39 ; 5335.42,3018.98 5361.88,3018.98 5348.65,2992.53 5335.42,3018.98 ; 5335.42,3190.95 5361.88,3190.95 5361.88,3217.4 5335.42,3217.4 5335.42,3190.95
  lines w12: 5286,2259.47 8395.46,2259.47 ; 5286,3350.79 8395.46,3350.79 ; 5601.13,2160.26 5601.13,3450 ; 5917.88,2160.26 5917.88,3450 ; 6538.9,2160.26 6538.9,3450 ; 6782.83,2160.26 6782.83,3450 ; 7142.73,2160.26 7142.73,3450 ; 7851.88,2160.26 7851.88,3450 ; 5286,2160.26 8395.46,2160.26 8395.46,3450 5286,3450 5286,2160.26
  text "Symbol" at 5345.53,3380.55 h72
  text "Quantity" at 5630.9,3380.55 h72
  text "Finished Hole Size" at 5947.64,3380.55 h72
  text "Plated" at 6568.66,3380.55 h72
  text "Hole Type" at 6812.59,3380.55 h72
  text "Drill Layer Pair" at 7172.49,3380.55 h72
  text "Hole Tolerance" at 7881.64,3380.55 h72
  text "5" at 5630.9,3281.34 h60
  text "7.87mil (0.200mm)" at 5947.64,3281.34 h60
  text "PTH" at 6568.66,3281.34 h60
  text "Round" at 6812.59,3281.34 h60
  text "Top Layer - Bottom Layer" at 7172.49,3281.34 h60
  text "415" at 5630.9,3182.13 h60
  text "10.00mil (0.254mm)" at 5947.64,3182.13 h60
  text "PTH" at 6568.66,3182.13 h60
  text "Round" at 6812.59,3182.13 h60
  text "Top Layer - Bottom Layer" at 7172.49,3182.13 h60
  text "10" at 5630.9,3082.92 h60
  text "27.56mil (0.700mm)" at 5947.64,3082.92 h60
  text "PTH" at 6568.66,3082.92 h60
  text "Round" at 6812.59,3082.92 h60
  text "Top Layer - Bottom Layer" at 7172.49,3082.92 h60
  text "3" at 5630.9,2983.71 h60
  text "35.04mil (0.890mm)" at 5947.64,2983.71 h60
  text "PTH" at 6568.66,2983.71 h60
  text "Round" at 6812.59,2983.71 h60
  text "Top Layer - Bottom Layer" at 7172.49,2983.71 h60
  text "4" at 5630.9,2884.5 h60
  text "40.00mil (1.016mm)" at 5947.64,2884.5 h60
  text "PTH" at 6568.66,2884.5 h60
  text "Round" at 6812.59,2884.5 h60
  text "Top Layer - Bottom Layer" at 7172.49,2884.5 h60
  text "1" at 5630.9,2785.29 h60
  text "46.50mil (1.181mm)" at 5947.64,2785.29 h60
  text "PTH" at 6568.66,2785.29 h60
  text "Round" at 6812.59,2785.29 h60
  text "Top Layer - Bottom Layer" at 7172.49,2785.29 h60
  text "3" at 5630.9,2686.07 h60
  text "49.21mil (1.250mm)" at 5947.64,2686.07 h60
  text "PTH" at 6568.66,2686.07 h60
  text "Round" at 6812.59,2686.07 h60
  text "Top Layer - Bottom Layer" at 7172.49,2686.07 h60
  text "1" at 5630.9,2586.86 h60
  text "59.06mil (1.500mm)" at 5947.64,2586.86 h60
  text "PTH" at 6568.66,2586.86 h60
  text "Round" at 6812.59,2586.86 h60
  text "Top Layer - Bottom Layer" at 7172.49,2586.86 h60
  text "2" at 5630.9,2487.65 h60
  text "63.00mil (1.600mm)" at 5947.64,2487.65 h60
  text "PTH" at 6568.66,2487.65 h60
  text "Round" at 6812.59,2487.65 h60
  text "Top Layer - Bottom Layer" at 7172.49,2487.65 h60
  text "3" at 5630.9,2388.44 h60
  text "103.15mil (2.620mm)" at 5947.64,2388.44 h60
  text "PTH" at 6568.66,2388.44 h60
  text "Round" at 6812.59,2388.44 h60
  text "Top Layer - Bottom Layer" at 7172.49,2388.44 h60
  text "4" at 5630.9,2289.23 h60
  text "125.98mil (3.200mm)" at 5947.64,2289.23 h60
  text "PTH" at 6568.66,2289.23 h60
  text "Round" at 6812.59,2289.23 h60
  text "Top Layer - Bottom Layer" at 7172.49,2289.23 h60
  text "451 Total" at 5630.9,2190.02 h60
  text ".Layer_Name" at 577,-858.49 h60
M17 Embedded Cavity:
  text ".Layer_Name" at 577,-858.49 h60
M18 Embedded Assembly:
  text ".Layer_Name" at 577,-858.49 h60
M19 Embedded Keepout:
  text ".Layer_Name" at 577,-858.49 h60

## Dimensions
0,-400 to 1000,-400 on M2 Board Dimensions
4100,0 to 0,0 on M2 Board Dimensions
0,0 to 0,1700 on M2 Board Dimensions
